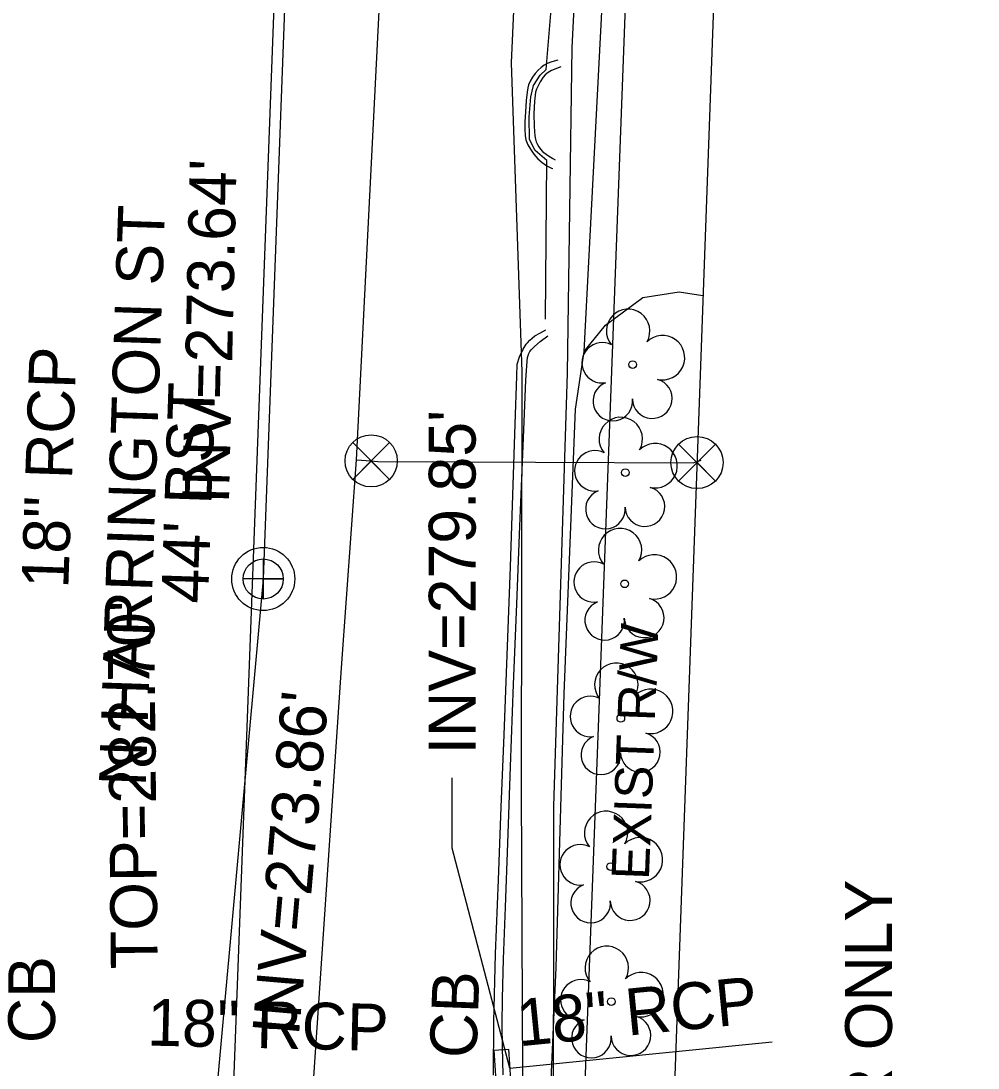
# Model space of a CAD drawing. Extents: x 2100323 to 2109811, y 740376 to 749755.
# Drawn here: x 2105413.2 to 2105494.9, y 741233.8 to 741323.2 of the extents above; entities that cross this region are included whole.
import ezdxf

# ---------------------------------------------------------------- set-up
doc = ezdxf.new("R2010")
doc.units = 0
for name, color, linetype in [('Exist Building', 7, 'Continuous'), ('Exist Horizontal Alignment', 7, 'Continuous'), ('Exist Right of Way Line', 7, 'Continuous'), ('Exist Right of Way Line Text', 7, 'Continuous'), ('Exist Roads Curbs', 7, 'Continuous'), ('Exist Roads EOP', 7, 'Continuous'), ('Exist Roads EOP Other', 7, 'Continuous'), ('Exist Roads EOP Text', 7, 'Continuous'), ('Exist Structure Minor Catch Basin', 7, 'Continuous'), ('Exist Structure Minor Catch Basin Text', 7, 'Continuous'), ('Exist Structure Minor Pipes HDPE 8 Inch Invert', 7, 'Continuous'), ('Exist Structure Minor Pipes RCP 18 Inch', 7, 'Continuous'), ('Exist Structure Minor Pipes RCP 18 Inch Invert', 7, 'Continuous'), ('Exist Structure Minor Pipes RCP 18 Inch Leader', 7, 'Continuous'), ('Exist Structure Minor Pipes RCP 18 Inch Text', 7, 'Continuous'), ('Exist Utilities Sanitary Sewer Manhole CELL', 7, 'Continuous'), ('Exist Utilities Sanitary Sewer Manhole Text', 7, 'Continuous'), ('Exist Utilities Sanitary Sewer UG Line', 7, 'Continuous'), ('Exist Utilities Sanitary Sewer UG Line Invert Elevation', 7, 'Continuous'), ('Exist Utilities Telephone UG Conduit SUE LOS B', 7, 'Continuous'), ('Exist Utilities TV UG Cable SUE LOS B', 7, 'Continuous'), ('Exist Utilities Water UG Line SUE LOS B', 7, 'Continuous'), ('Exist Utilities Water Valve CELL', 7, 'Continuous'), ('Exist Vegetation Tree CELL', 7, 'Continuous')]:
    doc.layers.add(name, color=color, linetype=linetype)

msp = doc.modelspace()

# ---------------------------------------------------------------- linework, layer by layer
at = {"layer": 'Exist Building'}
msp.add_lwpolyline([(2105655.872, 740941.303), (2105665.049, 741183.273), (2105694.647, 741194.61), (2105695.871, 741229.746), (2105667.111, 741242.972), (2105668.731, 741285.341), (2105616.78, 741287.218), (2105618.25, 741332.945), (2105472.817, 741337.856), (2105463.981, 741093.773), (2105542.406, 741091.192), (2105541.811, 741072.307), (2105556.774, 741071.846), (2105555.881, 741041.914), (2105581.429, 741040.986), (2105583.305, 741091.809), (2105607.195, 741091.081), (2105601.65, 740943.209)], close=True, dxfattribs=at)
at = {"layer": 'Exist Horizontal Alignment'}
msp.add_line((2105428.673, 741161.721), (2105442.437, 741527.922), dxfattribs=at)
at = {"layer": 'Exist Right of Way Line'}
msp.add_line((2105458.652, 741160.595), (2105470.88, 741485.931), dxfattribs=at)
at = {"layer": 'Exist Roads Curbs'}
for points in [[(2105459.282, 741319.271), (2105458.491, 741318.955), (2105458.192, 741318.783), (2105457.957, 741318.6), (2105457.786, 741318.408), (2105457.529, 741318.006), (2105457.311, 741317.589), (2105457.216, 741317.374), (2105457.136, 741317.118), (2105457.025, 741316.357), (2105456.982, 741315.269), (2105456.998, 741314.17), (2105457.064, 741313.38), (2105457.115, 741313.1), (2105457.186, 741312.865), (2105457.283, 741312.643), (2105457.407, 741312.434), (2105457.557, 741312.238), (2105457.734, 741312.054), (2105458.142, 741311.725), (2105458.605, 741311.444), (2105458.812, 741311.344)], [(2105458.098, 741311.284), (2105457.1, 741312.139), (2105456.615, 741313.077), (2105456.589, 741315.017), (2105456.731, 741316.708), (2105456.945, 741317.696), (2105457.524, 741318.56), (2105458.035, 741319.047)], [(2105454.356, 741233.173), (2105454.289, 741235.552), (2105454.269, 741237.471), (2105454.303, 741239.712), (2105454.4, 741243.056), (2105454.556, 741247.495), (2105454.753, 741252.985), (2105454.987, 741259.518), (2105455.246, 741266.52), (2105455.514, 741273.416), (2105455.785, 741280.054), (2105456.009, 741285.523), (2105456.178, 741289.669), (2105456.305, 741292.527), (2105456.404, 741294.132), (2105456.443, 741294.464), (2105456.488, 741294.636), (2105456.553, 741294.801), (2105456.639, 741294.958), (2105456.746, 741295.108), (2105457.036, 741295.405), (2105457.523, 741295.814), (2105458.164, 741296.31)]]:
    msp.add_lwpolyline(points, dxfattribs=at)
at = {"layer": 'Exist Roads EOP'}
for points in [[(2105459.035, 741319.855), (2105458.516, 741319.702), (2105458.13, 741319.555), (2105457.861, 741319.408), (2105457.604, 741319.218), (2105457.342, 741318.98), (2105457.089, 741318.7), (2105456.864, 741318.386), (2105456.67, 741318.047), (2105456.533, 741317.746), (2105456.456, 741317.492), (2105456.403, 741317.102), (2105456.336, 741316.392), (2105456.263, 741315.424), (2105456.222, 741314.578), (2105456.219, 741313.917), (2105456.25, 741313.414), (2105456.307, 741313.044), (2105456.346, 741312.909), (2105456.473, 741312.628), (2105456.684, 741312.256), (2105456.973, 741311.813), (2105457.31, 741311.42), (2105457.688, 741311.094), (2105458.084, 741310.834), (2105458.476, 741310.635), (2105458.615, 741310.58)], [(2105453.527, 741233.157), (2105453.549, 741237.725), (2105453.718, 741243.518), (2105453.96, 741249.854), (2105454.201, 741256.055), (2105454.443, 741262.229), (2105454.7, 741269.035), (2105454.973, 741276.583), (2105455.22, 741283.583), (2105455.396, 741288.746), (2105455.528, 741292.847), (2105455.561, 741293.892), (2105455.759, 741294.507), (2105456.074, 741295.151), (2105456.328, 741295.581), (2105456.431, 741295.714), (2105456.627, 741295.92), (2105456.833, 741296.109), (2105457.073, 741296.293), (2105457.493, 741296.543), (2105458.019, 741296.82)]]:
    msp.add_lwpolyline(points, dxfattribs=at)
at = {"layer": 'Exist Roads EOP Other'}
for points in [[(2105461.283, 741294.966), (2105463.322, 741334.382)], [(2105458.035, 741319.047), (2105459.217, 741333.417)], [(2105457.974, 741297.723), (2105458.098, 741311.284)], [(2105420.362, 741006.883), (2105428.598, 741027.868), (2105433.114, 741039.624), (2105437.269, 741052.183), (2105441.175, 741064.97), (2105444.58, 741079.319), (2105448.694, 741097.124), (2105451.78, 741115.06), (2105454.133, 741131.248), (2105455.339, 741145.065), (2105456.142, 741163.54), (2105456.984, 741182.891), (2105457.489, 741211.079), (2105458.874, 741242.339), (2105459.571, 741265.737), (2105460.531, 741290.026), (2105461.283, 741294.966), (2105463.104, 741297.2), (2105466.29, 741299.563), (2105469.41, 741300.046), (2105471.429, 741299.759)]]:
    msp.add_lwpolyline(points, dxfattribs=at)
at = {"layer": 'Exist Structure Minor Catch Basin'}
msp.add_lwpolyline([(2105454.821, 741235.376), (2105455.152, 741230.128), (2105453.928, 741230.05), (2105453.597, 741235.299)], close=True, dxfattribs=at)
at = {"layer": 'Exist Structure Minor Pipes RCP 18 Inch'}
msp.add_line((2105454.933, 741233.769), (2105477.331, 741235.994), dxfattribs=at)
at = {"layer": 'Exist Structure Minor Pipes RCP 18 Inch Leader'}
msp.add_lwpolyline([(2105454.933, 741233.769), (2105450.004, 741252.555), (2105450.004, 741258.555)], dxfattribs=at)
at = {"layer": 'Exist Utilities Sanitary Sewer Manhole CELL'}
msp.add_lwpolyline([(2105433.861, 741277.246), (2105433.861, 741273.821), (2105433.861, 741275.534), (2105435.573, 741275.534), (2105432.149, 741275.534)], dxfattribs=at)
for radius in [2.694, 1.712]:
    msp.add_circle((2105433.861, 741275.534), radius, dxfattribs=at)
at = {"layer": 'Exist Utilities Sanitary Sewer UG Line'}
msp.add_line((2105433.862, 741275.516), (2105415.799, 741077.039), dxfattribs=at)
msp.add_lwpolyline([(2105443.22, 741525.775), (2105433.86, 741275.552)], dxfattribs=at)
at = {"layer": 'Exist Utilities Telephone UG Conduit SUE LOS B'}
msp.add_lwpolyline([(2105409.973, 740988.51), (2105417.219, 741007.774), (2105433.129, 741048.489), (2105441.733, 741074.713), (2105447.227, 741097.264), (2105449.072, 741104.025), (2105452.794, 741109.996), (2105458.055, 741133.997), (2105460.761, 741166.356), (2105457.858, 741172.091), (2105457.496, 741199.513), (2105456.111, 741220.878), (2105455.912, 741257.492), (2105455.973, 741293.232), (2105455.081, 741319.615), (2105456.211, 741344.988), (2105459.282, 741370.216), (2105460.596, 741411.261), (2105461.649, 741450.115), (2105462.689, 741487.661), (2105462.808, 741511.512), (2105467.685, 741548.632), (2105471.24, 741572.815), (2105472.306, 741596.961)], dxfattribs=at)
at = {"layer": 'Exist Utilities TV UG Cable SUE LOS B'}
msp.add_lwpolyline([(2105463.819, 741118.145), (2105457.184, 741122.715), (2105455.653, 741128.348), (2105459.042, 741167.035), (2105459.211, 741197.143), (2105458.646, 741220.585), (2105458.678, 741256.143), (2105459.852, 741293.101), (2105460.256, 741320.911), (2105461.612, 741348.332), (2105463.807, 741379.765), (2105466.276, 741414.998), (2105467.036, 741435.714), (2105468.095, 741459.492), (2105468.629, 741477.044)], dxfattribs=at)
at = {"layer": 'Exist Utilities Water UG Line SUE LOS B'}
msp.add_line((2105470.581, 741285.466), (2105471.281, 741285.694), dxfattribs=at)
for points in [[(2105367.461, 740858.99), (2105373.13, 740890.868), (2105378.201, 740917.261), (2105384.014, 740942.048), (2105390.698, 740965.749), (2105394.076, 740976.267), (2105395.239, 740980.055), (2105408.104, 741022.381), (2105409.264, 741025.395), (2105417.62, 741054.982), (2105422.429, 741078.211), (2105426.878, 741109.927), (2105433.682, 741162.954), (2105435.306, 741190.47), (2105440.534, 741267.943), (2105441.828, 741285.723), (2105443.974, 741328.028), (2105444.771, 741359.32), (2105447.086, 741417.47), (2105447.153, 741419.519), (2105449.793, 741492.293), (2105450.102, 741505.565), (2105450.55, 741529.385), (2105450.667, 741531.011)], [(2105441.828, 741285.723), (2105443.084, 741285.62), (2105443.638, 741285.576), (2105470.581, 741285.466)]]:
    msp.add_lwpolyline(points, dxfattribs=at)
at = {"layer": 'Exist Utilities Water Valve CELL'}
for points in [[(2105444.659, 741287.195), (2105441.509, 741284.045), (2105443.084, 741285.62), (2105444.659, 741284.045), (2105441.509, 741287.195)], [(2105472.496, 741287.052), (2105469.346, 741283.902), (2105470.921, 741285.477), (2105472.496, 741283.902), (2105469.346, 741287.052)]]:
    msp.add_lwpolyline(points, dxfattribs=at)
for centre in [(2105443.084, 741285.62), (2105470.921, 741285.477)]:
    msp.add_circle(centre, 2.227, dxfattribs=at)
at = {"layer": 'Exist Vegetation Tree CELL'}
for p, q in [((2105465.424, 741293.847), (2105465.424, 741293.847)), ((2105464.796, 741284.62), (2105464.796, 741284.62)), ((2105464.735, 741275.122), (2105464.735, 741275.122)), ((2105464.412, 741263.636), (2105464.412, 741263.636)), ((2105463.54, 741250.972), (2105463.54, 741250.972)), ((2105463.6, 741239.443), (2105463.6, 741239.443))]:
    msp.add_line(p, q, dxfattribs=at)
for centre in [(2105465.424, 741293.847), (2105464.796, 741284.62), (2105464.735, 741275.122), (2105464.412, 741263.636), (2105463.54, 741250.972), (2105463.6, 741239.443)]:
    msp.add_circle(centre, 0.326, dxfattribs=at)
for centre, radius, start, end in [((2105465.039, 741296.721), 1.856, 330.16508, 219.71335), ((2105467.973, 741294.436), 1.899, 257.1011, 134.19993), ((2105462.818, 741294.001), 1.727, 62.66361, 279.3457), ((2105467.097, 741290.948), 1.698, 181.28216, 74.55999), ((2105463.72, 741290.727), 1.689, 111.56708, 6.23104), ((2105464.411, 741287.493), 1.856, 330.16508, 219.71335), ((2105467.345, 741285.208), 1.899, 257.1011, 134.19993), ((2105462.19, 741284.773), 1.727, 62.66361, 279.3457), ((2105463.092, 741281.499), 1.689, 111.56708, 6.23104), ((2105466.469, 741281.72), 1.698, 181.28216, 74.55999), ((2105464.35, 741277.996), 1.856, 330.16508, 219.71335), ((2105467.284, 741275.711), 1.899, 257.1011, 134.19993), ((2105462.13, 741275.276), 1.727, 62.66361, 279.3457), ((2105466.408, 741272.223), 1.698, 181.28216, 74.55999), ((2105463.031, 741272.002), 1.689, 111.56708, 6.23104), ((2105464.028, 741266.509), 1.856, 330.16508, 219.71335), ((2105466.961, 741264.225), 1.899, 257.1011, 134.19993), ((2105461.807, 741263.79), 1.727, 62.66361, 279.3457), ((2105462.708, 741260.515), 1.689, 111.56708, 6.23104), ((2105466.085, 741260.736), 1.698, 181.28216, 74.55999), ((2105463.156, 741253.845), 1.856, 330.16508, 219.71335), ((2105466.089, 741251.561), 1.899, 257.1011, 134.19993), ((2105460.935, 741251.126), 1.727, 62.66361, 279.3457), ((2105465.213, 741248.073), 1.698, 181.28216, 74.55999), ((2105461.836, 741247.851), 1.689, 111.56708, 6.23104), ((2105463.215, 741242.317), 1.856, 330.16508, 219.71335), ((2105466.148, 741240.032), 1.899, 257.1011, 134.19993), ((2105460.994, 741239.597), 1.727, 62.66361, 279.3457), ((2105461.895, 741236.322), 1.689, 111.56708, 6.23104), ((2105465.272, 741236.544), 1.698, 181.28216, 74.55999)]:
    msp.add_arc(centre, radius, start, end, dxfattribs=at)

# ---------------------------------------------------------------- texts
at = {"layer": 'Exist Right of Way Line Text'}
msp.add_text('EXIST R/W', height=3.2, rotation=87.84754, dxfattribs=at).set_placement((2105466.809, 741249.811))
at = {"layer": 'Exist Roads EOP Text'}
for s, p in [('N HARRINGTON ST', (2105423.814, 741257.788)), ("44' BST", (2105429.139, 741273.398))]:
    msp.add_text(s, height=4, rotation=88.08404, dxfattribs=at).set_placement(p)
at = {"layer": 'Exist Structure Minor Catch Basin Text'}
for rotation, p in [(90, (2105416.073, 741235.894)), (87.75986, (2105452.063, 741234.553))]:
    msp.add_text('CB', height=4, rotation=rotation, dxfattribs=at).set_placement(p)
at = {"layer": 'Exist Structure Minor Pipes HDPE 8 Inch Invert'}
msp.add_text('DIR ONLY', height=4, rotation=90, dxfattribs=at).set_placement((2105487.58, 741224.582))
at = {"layer": 'Exist Structure Minor Pipes RCP 18 Inch Invert'}
msp.add_text("INV=279.85'", height=4, rotation=90, dxfattribs=at).set_placement((2105452.004, 741260.555))
at = {"layer": 'Exist Structure Minor Pipes RCP 18 Inch Text'}
for rotation, p in [(88.05719, (2105417.201, 741274.682)), (5.61683, (2105455.71, 741235.614)), (358.70259, (2105423.91, 741235.69))]:
    msp.add_text('18" RCP', height=4, rotation=rotation, dxfattribs=at).set_placement(p)
at = {"layer": 'Exist Utilities Sanitary Sewer Manhole Text'}
msp.add_text("TOP=282.70'", height=4, rotation=90.56691, dxfattribs=at).set_placement((2105424.842, 741242.241))
at = {"layer": 'Exist Utilities Sanitary Sewer UG Line Invert Elevation'}
for s, rotation, p in [("INV=273.64'", 88.71349, (2105430.93, 741281.933)), ("INV=273.86'", 85.02158, (2105436.902, 741236.432))]:
    msp.add_text(s, height=4, rotation=rotation, dxfattribs=at).set_placement(p)

doc.saveas('drawing.dxf')
